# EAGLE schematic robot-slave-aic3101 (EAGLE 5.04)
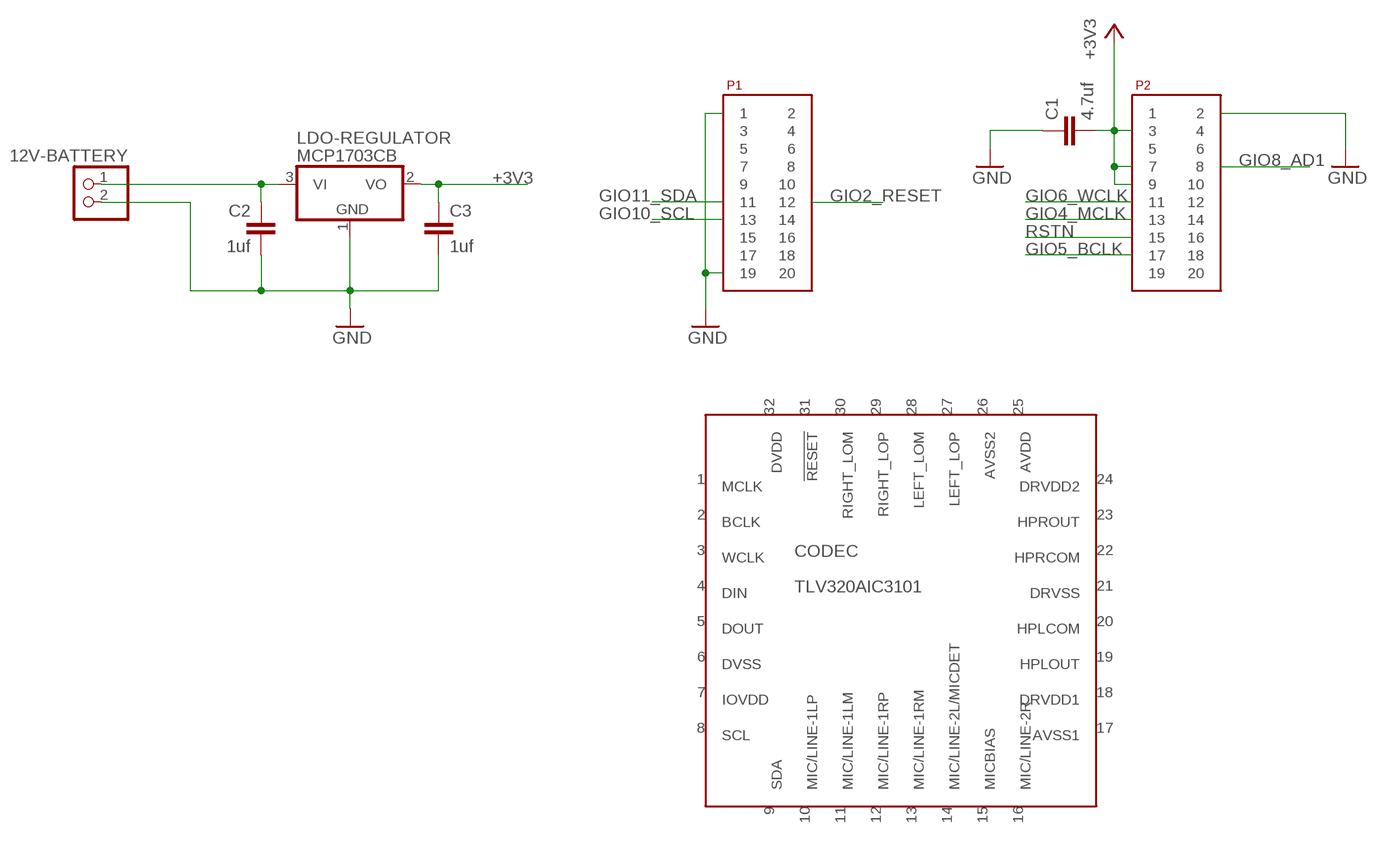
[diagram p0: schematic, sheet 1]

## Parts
12V-BATTERY  PINHD-1X2  [1X02]
C1  4.7uf  C-EUC1206  [C1206]
C2  1uf  C-EUC1206  [C1206]
C3  1uf  C-EUC1206  [C1206]
CODEC  TLV320AIC3101  [SCHMARTBOARD-VQFN32]
LDO-REGULATOR  MCP1703CB  [SOT23]
P1  SAMTEC-10X2  [SAMTEC-10X2]
P2  SAMTEC-10X2  [SAMTEC-10X2]

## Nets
+3V3: C1.2 C3.1 LDO-REGULATOR.2(VO) P2.3 P2.7 P2.9
GIO2_RESET: P1.12
GIO4_MCLK: P2.13
GIO5_BCLK: P2.17
GIO6_WCLK: P2.11
GIO8_AD1: P2.8
GIO10_SCL: P1.13
GIO11_SDA: P1.11
GND: 12V-BATTERY.2 C1.1 C2.2 C3.2 LDO-REGULATOR.1(GND) P1.1 P1.19 P2.2
N$1: 12V-BATTERY.1 C2.1 LDO-REGULATOR.3(VI)
RSTN: P2.15
Unconnected: CODEC.1(MCLK) CODEC.2(BCLK) CODEC.3(WCLK) CODEC.4(DIN) CODEC.5(DOUT) CODEC.6(DVSS) CODEC.7(IOVDD) CODEC.8(SCL) CODEC.9(SDA) CODEC.10(MIC/LINE-1LP) CODEC.11(MIC/LINE-1LM) CODEC.12(MIC/LINE-1RP) CODEC.13(MIC/LINE-1RM) CODEC.14(MIC/LINE-2L/MICDET) CODEC.15(MICBIAS) CODEC.16(MIC/LINE-2R) CODEC.17(AVSS1) CODEC.18(DRVDD1) CODEC.19(HPLOUT) CODEC.20(HPLCOM) CODEC.21(DRVSS) CODEC.22(HPRCOM) CODEC.23(HPROUT) CODEC.24(DRVDD2) CODEC.25(AVDD) CODEC.26(AVSS2) CODEC.27(LEFT_LOP) CODEC.28(LEFT_LOM) CODEC.29(RIGHT_LOP) CODEC.30(RIGHT_LOM) CODEC.31(!RESET) CODEC.32(DVDD) P1.2 P1.3 P1.4 P1.5 P1.6 P1.7 P1.8 P1.9 P1.10 P1.14 P1.15 P1.16 P1.17 P1.18 P1.20 P2.1 P2.4 P2.5 P2.6 P2.10 P2.12 P2.14 P2.16 P2.18 P2.19 P2.20

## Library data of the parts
12V-BATTERY = pinhead:PINHD-1X2: PIN HEADER
C1-C3 = rcl:C-EU: CAPACITOR, European symbol
CODEC = trl:TLV320AIC3101
LDO-REGULATOR = linear:MCP1703: 250 mA, 16V, Low Quiescent Current LDO Regulator Source: http://ww1.microchip.com/downloads/en/DeviceDoc/22049b.pdf
P1 P2 = trl:SAMTEC-10X2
